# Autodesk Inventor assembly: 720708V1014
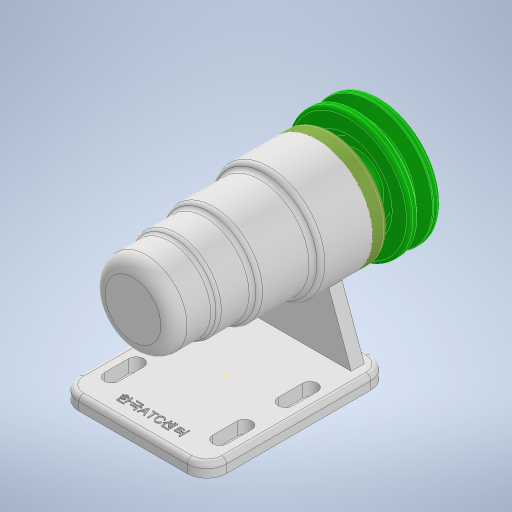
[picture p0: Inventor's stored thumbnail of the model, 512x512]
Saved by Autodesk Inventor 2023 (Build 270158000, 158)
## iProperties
Created: 2022-07
Part Number: 720708V1014
Document SubType Name: Assembly
Designer: owner
Author: owner
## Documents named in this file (12)
- C:\Users\owner\Desktop\720708V1014\720708V1014.iam
- C:\Users\owner\Desktop\720708V1014\본체.ipt
- C:\Users\owner\Desktop\720708V1014\V벨트풀리.ipt
- C:\Users\owner\Desktop\720708V1014\멈춤나사 M3.ipt
- C:\Users\owner\Desktop\720708V1014\베어링 6004.ipt
- C:\Users\owner\Desktop\720708V1014\베어링 51202.ipt
- C:\Users\owner\Desktop\720708V1014\볼트 M4.ipt
- C:\Users\owner\Desktop\720708V1014\어댑터슬리브.ipt
- C:\Users\owner\Desktop\720708V1014\오일 실 20x35x7.ipt
- C:\Users\owner\Desktop\720708V1014\축.ipt
- C:\Users\owner\Desktop\720708V1014\커버.ipt
- C:\Users\owner\Desktop\720708V1014\키 5x5.ipt
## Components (1 placed, 1 different names)
1. V벨트풀리:1 — 강체:6
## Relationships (1: WeldJoint 1)
- 강체:6 [WeldJoint]: V벨트풀리:1
